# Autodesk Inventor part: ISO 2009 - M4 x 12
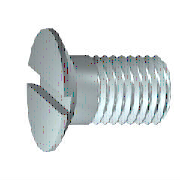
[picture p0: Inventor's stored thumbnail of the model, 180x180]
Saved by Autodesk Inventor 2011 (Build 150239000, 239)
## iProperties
Created: 2010-02
Part Number: ISO 2009 - M4 x 12
Material: EdelStahl - 440C
Description: Senkkopfschrauben mit Schlitz (Einheitskopf) - Produktklasse A
Document SubType Name: Modeling
Standard: ISO 2009
Designer: M.Schulte
Standard Revision: Third edition 1994-04-01
Standards Organization: ISO
Language: de-DE
Size Designation: M4 x 12 x 7,9
Categories: <MemberInstance><Categories><Category DisplayName="Verbindungselemente" InternalName="e4da775c-781d-43d5-af7c-5136215cf5a6" Mnemonic="FSTN"><Category DisplayNam
Density: 7.75 g/cm^3
IsCustomPart: 0
Author: M.Schulte
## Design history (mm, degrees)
body "Solid1"
sketch "Sketch1"
  geometry: L1 (3.129, 1.571)-(0.5, 4.2); L2 (0.5, 4.2)-(0, 4.2); L3 (0, 4.2)-(0, 0); L4 (0, 0)-(12, 0); L5 (12, 2)-(4.1, 2); L6 (4.1, 2)-(3.671, 1.571); L7 (3.671, 1.571)-(3.129, 1.571); L8 (4.1, 2)-(2.7, 2); L9 (12, 0)-(12, 2); L10 (-2.4, 0)-(14.4, 0) reference; L11 (0, 5.04)-(0, -0.84) reference
  constraints: 18 end point, 4 parallel, 2 collinear, 2 perpendicular, 1 horizontal, 1 point on line
  dimensions: "d0" = 12 distance of L3.end L4.end (= NLG); "d1" = 45 deg angle of L1 L4 (= 0.5 x SEWI); "d2" = 0.42941 horizontal distance of L5.end L6.end (= GAL); "d3" = 7.9 distance from line of L9 L5.end (= GEL); "d4" = 2.7 distance from line of L8.end L3 (= KOH); "d5" = 3.14117 diameter of L6.end L4 (= BDM); "d6" = 4 diameter of L5 L4 (= GD); "d7" = 8.4 diameter of L2 L4 (= KOD)
workplane "Work Plane1"
revolve "Body" stored, may be unused: angle "d19" = 90 deg
sketch "Sketch2"
  geometry: L1 (4.2, -0.755)-(-4.2, -0.755); L2 (-4.2, -0.755)-(-4.2, 0.755); L3 (-4.2, 0.755)-(4.2, 0.755); L4 (4.2, 0.755)-(4.2, -0.755); L5 (0, 0.755)-(0, -0.755); L6 (-4.2, 0)-(4.2, 0); L7 (0, 4.2)-(0, 0) reference; 2 further points
  constraints: 12 end point, 5 midpoint, 2 parallel, 1 collinear, 1 horizontal, 1 perpendicular
  dimensions: "d15" = 1.51 distance of L3.end L1.start (= SBR); "d16" = 8.4 distance of L1.start L1.end (= KOD)
extrude "Slot" cut sketch "Sketch2" distance "d8" = 1.3 (= STI); taper "d9" = 0 deg
feature "Thread" dims "d10" = 7.9 (= GEL), "d11" = 0
chamfer "Chamfer1" distance "d12" = 0.42941 (= -0.5 x SPD + 0.5 x GD); stored, may be unused: second distance "d13" = 0.21471 (= 0.5 x GAL), angle "d35" = 45 deg
other parameters: "NLG" = 12 [user parameter; used in 1 equation term], "GAL" = 0.42941 (= 0.61345 x PTC) [user parameter; used in 2 equation terms], "GEL" = 7.9 [user parameter; used in 2 equation terms], "KOH" = 2.7 [user parameter; used in 1 equation term], "KOD" = 8.4 [user parameter; used in 2 equation terms], "SEWI" = 90 deg [user parameter; used in 1 equation term], "BDM" = 3.14117 (= NND - 1.2269 x PTC) [user parameter; used in 1 equation term], "GD" = 4 (= NND) [user parameter; used in 2 equation terms], "SBR" = 1.51 [user parameter; used in 1 equation term], "STI" = 1.3 [user parameter; used in 1 equation term], "d17" = 0, "SPD" = 3.14117 (= NND - 1.2269 x PTC) [user parameter; used in 1 equation term], "d39" = 0, "d40" = 0, "GUL" = 0.42941 (= 0.61345 x PTC) [user parameter], "PTC" = 0.7 [user parameter; used in 6 equation terms], "EPV" = 4.7 [user parameter], "THREADDIA" = 4 [user parameter; used in 1 equation term], "TOA" = 30 deg [user parameter], "TPU" = 14.28571 (computed from PTC) [user parameter], "NND" = 4 [user parameter; used in 3 equation terms], "GD1" = 3.14117 (= THREADDIA - 1.2269 x PTC) [user parameter]
